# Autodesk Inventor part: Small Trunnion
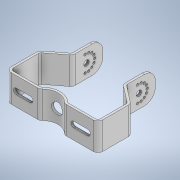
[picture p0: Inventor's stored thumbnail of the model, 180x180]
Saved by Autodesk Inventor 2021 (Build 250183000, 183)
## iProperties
Created: 2020-07
Part Number: Small Trunnion
Material: Generic
Description: STEP AP203
Document SubType Name: Modeling
Designer: DarrinWoodcock
Density: 1 g/cm^3
Appearance: Default
Title: Ð¡UÐÍÌú.STEP
Author: admin
Sending System: SolidWorks 2016
Preprocessor: SwSTEP 2.0
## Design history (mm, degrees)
feature "UÐÍÌú_1:1"
body "Solid1"
